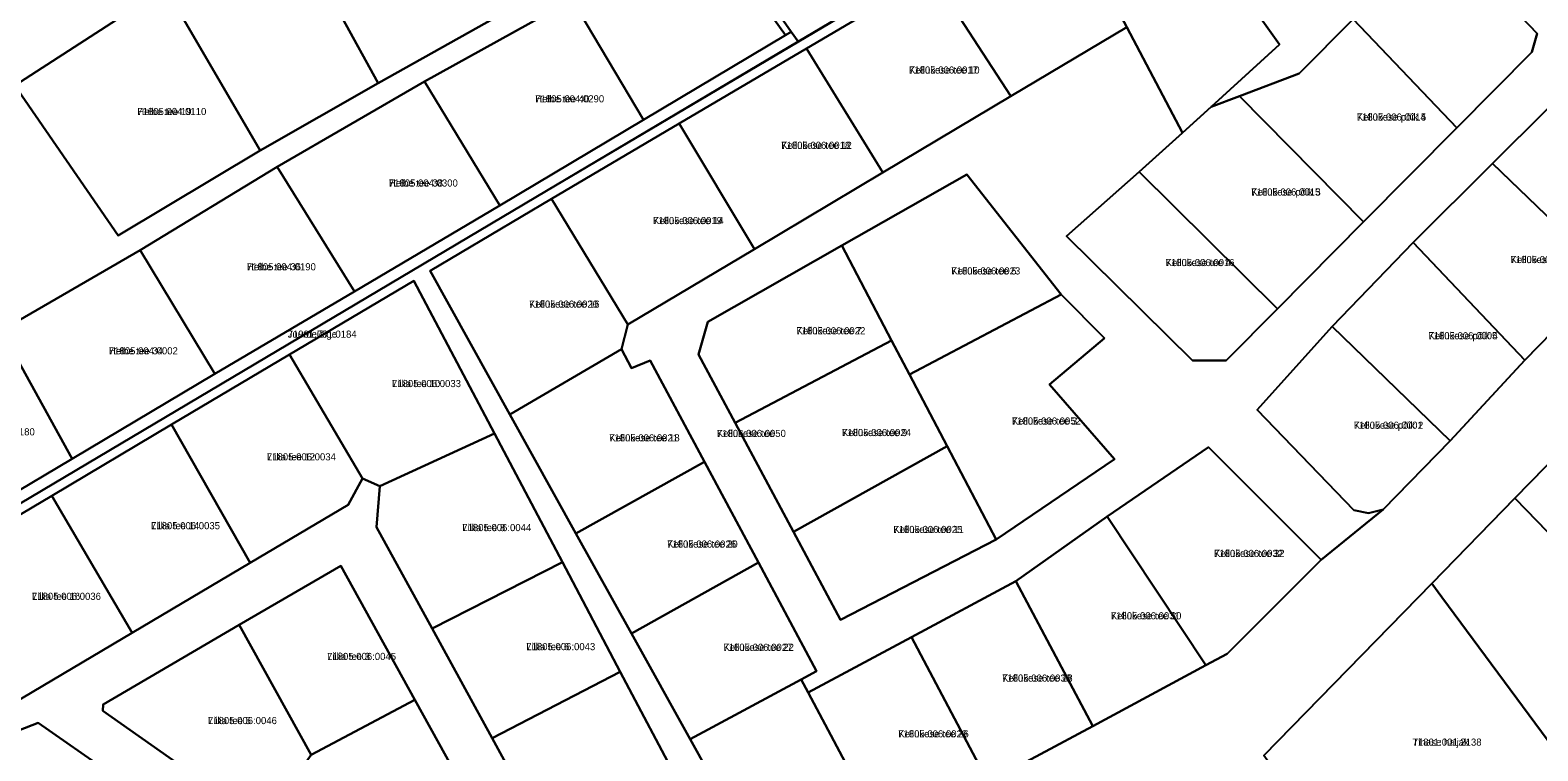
# Model space of a CAD drawing. Extents: x 529768 to 552006, y 6562269 to 6580975.
# Drawn here: x 537375.5 to 537692.6, y 6571224.9 to 6571376.5 of the extents above; entities that cross this region are included whole.
import ezdxf

# ---------------------------------------------------------------- set-up
doc = ezdxf.new("R2010")
doc.units = 0
for name, color, linetype in [('L_AADRESS', 7, 'Continuous'), ('PIIR', 7, 'Continuous'), ('TUNNUS', 7, 'Continuous')]:
    doc.layers.add(name, color=color, linetype=linetype)

msp = doc.modelspace()

# ---------------------------------------------------------------- linework, layer by layer
at = {"layer": 'PIIR'}
for points in [[(537702.86, 6571472.26), (537537.01, 6571374.1), (537535.57, 6571376.16), (537390.22, 6571584.9), (537364.81, 6571621.35)], [(537375.33, 6571521.4), (537398.03, 6571534.85), (537402.31, 6571540.45), (537378.19, 6571577.21), (537380.85, 6571578.91), (537390.22, 6571584.9), (537535.57, 6571376.16), (537534.34, 6571375.44), (537509.23, 6571410.51), (537508.1, 6571395.88), (537489.48, 6571382.98), (537458.45, 6571365.69), (537427.46, 6571347.74), (537398.65, 6571330.25), (537369.5, 6571313.34)], [(537362.92, 6571428.14), (537383.38, 6571396.32), (537393.59, 6571403.57), (537404.02, 6571385.41), (537372.3, 6571364.86), (537394.07, 6571333.31), (537423.89, 6571351.18), (537448.72, 6571365.38), (537475.12, 6571380.13), (537495.26, 6571392.55), (537500.44, 6571398.27), (537500.24, 6571405.38), (537484.63, 6571429.61), (537466.68, 6571455.44), (537448.53, 6571481.33), (537430.06, 6571506.65), (537412.22, 6571531.24), (537404.55, 6571531.74), (537378.26, 6571517.21), (537372.52, 6571514.07)], [(537512.12, 6571217.83), (537499.61, 6571241.55), (537487.46, 6571264.58), (537473.18, 6571291.64), (537456.21, 6571323.81), (537430.08, 6571308.29), (537405.24, 6571293.53), (537380.07, 6571278.58), (537354.9, 6571263.63), (537324.81, 6571245.7), (537323.81, 6571247.48), (537484.12, 6571342.72), (537702.86, 6571472.26)], [(537694.4, 6571359.72), (537683, 6571348.48), (537666.32, 6571331.83), (537649.3, 6571314.15), (537633.57, 6571296.66), (537653.88, 6571275.57), (537656.93, 6571274.93), (537660.06, 6571275.7), (537646.99, 6571265.1), (537623.28, 6571288.76), (537601.98, 6571274.19), (537582.81, 6571260.61), (537560.86, 6571248.83), (537539.13, 6571237.16), (537537.66, 6571239.95), (537540.92, 6571241.7), (537528.69, 6571264.52), (537517.34, 6571285.71), (537505.93, 6571307), (537502, 6571305.38), (537499.9, 6571309.41), (537501.25, 6571314.58), (537527.84, 6571330.44), (537554.85, 6571346.55), (537581.77, 6571362.6), (537606.13, 6571377.13), (537617.87, 6571354.91), (537608.71, 6571346.73), (537593.49, 6571333.16), (537619.94, 6571307.02), (537627.04, 6571307.05), (537637.81, 6571317.91), (537655.91, 6571336.16), (537675.56, 6571355.97), (537691.33, 6571371.87), (537692.43, 6571375.8), (537672.05, 6571397.14)], [(537565.14, 6571388.2), (537538.79, 6571372.65), (537512.01, 6571356.85), (537485.14, 6571341), (537459.65, 6571325.86), (537476.39, 6571295.7), (537490.32, 6571270.6), (537501.97, 6571249.62), (537514.31, 6571227.38), (537532.58, 6571194.47)], [(537577.01, 6571218.34), (537598.96, 6571230.13), (537622.75, 6571242.92), (537627.21, 6571245.31), (537646.99, 6571265.1), (537660.06, 6571275.7), (537674.15, 6571290.11), (537689.8, 6571307.09), (537707.34, 6571325.07)], [(537703.9, 6571294.61), (537687.75, 6571278.06), (537670.25, 6571260.12), (537634.95, 6571223.95)]]:
    msp.add_lwpolyline(points, dxfattribs=at)
for points in [[(537429.05, 6571428.91), (537442.51, 6571411.27), (537449.05, 6571414.78), (537450.48, 6571415.52), (537455.2, 6571408.66), (537475.12, 6571380.13), (537448.72, 6571365.38), (537418.16, 6571420.97)], [(537404.02, 6571385.41), (537393.59, 6571403.57), (537401.64, 6571409.33), (537418.16, 6571420.97), (537448.72, 6571365.38), (537423.89, 6571351.18)], [(537638.27, 6571373.5), (537623.86, 6571360.37), (537617.87, 6571354.91), (537606.13, 6571377.13), (537591.93, 6571404.01), (537609.33, 6571414.28), (537629.35, 6571386.06)], [(537672.05, 6571397.14), (537653.72, 6571378.82), (537642.37, 6571367.41), (537629.8, 6571362.63), (537623.86, 6571360.37), (537638.27, 6571373.5), (537629.35, 6571386.06), (537656.65, 6571413.26)], [(537489.48, 6571382.98), (537508.1, 6571395.88), (537509.23, 6571410.51), (537534.34, 6571375.44), (537504.53, 6571357.68)], [(537606.13, 6571377.13), (537581.77, 6571362.6), (537565.14, 6571388.2), (537591.93, 6571404.01)], [(537692.43, 6571375.8), (537691.33, 6571371.87), (537675.56, 6571355.97), (537653.72, 6571378.82), (537672.05, 6571397.14)], [(537554.85, 6571346.55), (537538.79, 6571372.65), (537565.14, 6571388.2), (537581.77, 6571362.6)], [(537423.89, 6571351.18), (537394.07, 6571333.31), (537372.3, 6571364.86), (537404.02, 6571385.41)], [(537458.45, 6571365.69), (537489.48, 6571382.98), (537504.53, 6571357.68), (537474.31, 6571339.66)], [(537535.57, 6571376.16), (537537.01, 6571374.1), (537484.12, 6571342.72), (537323.81, 6571247.48), (537322.52, 6571249.63), (537331.04, 6571254.5), (537333.2, 6571254.45), (537355.55, 6571269.2), (537384.35, 6571286.37), (537414.4, 6571304.23), (537443.78, 6571321.53), (537474.31, 6571339.66), (537504.53, 6571357.68), (537534.34, 6571375.44)], [(537655.91, 6571336.16), (537629.8, 6571362.63), (537642.37, 6571367.41), (537653.72, 6571378.82), (537675.56, 6571355.97)], [(537527.84, 6571330.44), (537512.01, 6571356.85), (537538.79, 6571372.65), (537554.85, 6571346.55)], [(537427.46, 6571347.74), (537458.45, 6571365.69), (537474.31, 6571339.66), (537443.78, 6571321.53)], [(537722.98, 6571341.36), (537707.34, 6571325.07), (537683, 6571348.48), (537694.4, 6571359.72), (537700.86, 6571366.1), (537707.79, 6571359.49)], [(537637.81, 6571317.91), (537608.71, 6571346.73), (537617.87, 6571354.91), (537623.86, 6571360.37), (537629.8, 6571362.63), (537655.91, 6571336.16)], [(537501.25, 6571314.58), (537485.14, 6571341), (537512.01, 6571356.85), (537527.84, 6571330.44)], [(537398.65, 6571330.25), (537427.46, 6571347.74), (537443.78, 6571321.53), (537414.4, 6571304.23)], [(537689.8, 6571307.09), (537666.32, 6571331.83), (537683, 6571348.48), (537707.34, 6571325.07)], [(537601.48, 6571311.69), (537592.34, 6571320.94), (537572.47, 6571346.14), (537546.23, 6571331.19), (537518.07, 6571315.15), (537516.09, 6571308.27), (537523.77, 6571293.89), (537536.06, 6571270.98), (537545.97, 6571252.46), (537578.65, 6571269.35), (537603.53, 6571286.29), (537589.86, 6571301.96)], [(537572.47, 6571346.14), (537592.34, 6571320.94), (537560.44, 6571304.09), (537556.68, 6571311.26), (537546.23, 6571331.19)], [(537627.04, 6571307.05), (537619.94, 6571307.02), (537593.49, 6571333.16), (537608.71, 6571346.73), (537637.81, 6571317.91)], [(537499.9, 6571309.41), (537476.39, 6571295.7), (537459.65, 6571325.86), (537485.14, 6571341), (537501.25, 6571314.58)], [(537649.3, 6571314.15), (537666.32, 6571331.83), (537689.8, 6571307.09), (537674.15, 6571290.11)], [(537369.5, 6571313.34), (537398.65, 6571330.25), (537414.4, 6571304.23), (537384.35, 6571286.37)], [(537516.09, 6571308.27), (537518.07, 6571315.15), (537546.23, 6571331.19), (537556.68, 6571311.26), (537523.77, 6571293.89)], [(537473.18, 6571291.64), (537449.08, 6571280.61), (537445.42, 6571282.22), (537430.08, 6571308.29), (537456.21, 6571323.81)], [(537601.48, 6571311.69), (537589.86, 6571301.96), (537603.53, 6571286.29), (537578.65, 6571269.35), (537568.34, 6571289.02), (537560.44, 6571304.09), (537592.34, 6571320.94)], [(537342.32, 6571290.8), (537343.3, 6571297.87), (537369.5, 6571313.34), (537384.35, 6571286.37), (537355.55, 6571269.2)], [(537633.57, 6571296.66), (537649.3, 6571314.15), (537674.15, 6571290.11), (537660.06, 6571275.7), (537656.93, 6571274.93), (537653.88, 6571275.57)], [(537568.34, 6571289.02), (537536.06, 6571270.98), (537523.77, 6571293.89), (537556.68, 6571311.26), (537560.44, 6571304.09)], [(537445.42, 6571282.22), (537442.4, 6571276.69), (537421.84, 6571264.48), (537405.24, 6571293.53), (537430.08, 6571308.29)], [(537502, 6571305.38), (537505.93, 6571307), (537517.34, 6571285.71), (537490.32, 6571270.6), (537476.39, 6571295.7), (537499.9, 6571309.41)], [(537687.75, 6571278.06), (537703.9, 6571294.61), (537706.25, 6571292.01), (537736.91, 6571258.07), (537720.08, 6571244.65), (537690.18, 6571275.55)], [(537421.84, 6571264.48), (537396.97, 6571249.71), (537380.07, 6571278.58), (537405.24, 6571293.53)], [(537487.46, 6571264.58), (537460.05, 6571250.62), (537448.36, 6571271.95), (537449.08, 6571280.61), (537473.18, 6571291.64)], [(537578.65, 6571269.35), (537545.97, 6571252.46), (537536.06, 6571270.98), (537568.34, 6571289.02)], [(537601.98, 6571274.19), (537623.28, 6571288.76), (537646.99, 6571265.1), (537627.21, 6571245.31), (537622.75, 6571242.92)], [(537528.69, 6571264.52), (537501.97, 6571249.62), (537490.32, 6571270.6), (537517.34, 6571285.71)], [(537500.31, 6571177.14), (537489.99, 6571171.59), (537474.12, 6571163.07), (537443.9, 6571184.21), (537419.45, 6571201.31), (537395.3, 6571218.2), (537377.23, 6571230.84), (537343.75, 6571217.76), (537339.6, 6571220.7), (537371.86, 6571234.8), (537396.97, 6571249.71), (537421.84, 6571264.48), (537442.4, 6571276.69), (537445.42, 6571282.22), (537449.08, 6571280.61), (537448.36, 6571271.95), (537460.05, 6571250.62), (537472.66, 6571227.61), (537485.53, 6571204.11)], [(537396.97, 6571249.71), (537371.86, 6571234.8), (537354.9, 6571263.63), (537380.07, 6571278.58)], [(537670.25, 6571260.12), (537687.75, 6571278.06), (537690.18, 6571275.55), (537720.08, 6571244.65), (537695.95, 6571225.42), (537672.36, 6571257.27)], [(537582.81, 6571260.61), (537601.98, 6571274.19), (537622.75, 6571242.92), (537598.96, 6571230.13)], [(537390.85, 6571233.33), (537424.42, 6571209.69), (537460.83, 6571184.07), (537479.5, 6571193.94), (537456.44, 6571235.68), (537440.86, 6571263.86), (537419.53, 6571251.4), (537390.92, 6571234.67)], [(537440.86, 6571263.86), (537456.44, 6571235.68), (537434.62, 6571224.09), (537419.53, 6571251.4)], [(537499.61, 6571241.55), (537472.66, 6571227.61), (537460.05, 6571250.62), (537487.46, 6571264.58)], [(537540.92, 6571241.7), (537537.66, 6571239.95), (537514.31, 6571227.38), (537501.97, 6571249.62), (537528.69, 6571264.52)], [(537560.86, 6571248.83), (537582.81, 6571260.61), (537598.96, 6571230.13), (537577.01, 6571218.34)], [(537670.25, 6571260.12), (537672.36, 6571257.27), (537695.95, 6571225.42), (537696.81, 6571219.49), (537660.25, 6571193.6), (537657.8, 6571191.87), (537634.95, 6571223.95)], [(537390.85, 6571233.33), (537390.92, 6571234.67), (537419.53, 6571251.4), (537434.62, 6571224.09), (537424.42, 6571209.69)], [(537539.13, 6571237.16), (537560.86, 6571248.83), (537577.01, 6571218.34), (537555.3, 6571206.68)], [(537512.12, 6571217.83), (537485.53, 6571204.11), (537472.66, 6571227.61), (537499.61, 6571241.55)], [(537537.66, 6571239.95), (537539.13, 6571237.16), (537555.3, 6571206.68), (537532.58, 6571194.47), (537514.31, 6571227.38)], [(537479.5, 6571193.94), (537460.83, 6571184.07), (537424.42, 6571209.69), (537434.62, 6571224.09), (537456.44, 6571235.68)], [(537377.23, 6571230.84), (537395.3, 6571218.2), (537377.95, 6571193.89), (537365.05, 6571202.83), (537343.75, 6571217.76)]]:
    msp.add_lwpolyline(points, close=True, dxfattribs=at)

# ---------------------------------------------------------------- texts
at = {"layer": 'L_AADRESS'}
for s, p in [('Kellukese tee 10', (537560.35, 6571367.38)), ('Helbe tee 40', (537481.74, 6571361.32)), ('Helbe tee 19', (537398.09, 6571358.65)), ('Kellukese põik 5', (537654.49, 6571357.49)), ('Kellukese tee 12', (537533.48, 6571351.54)), ('Helbe tee 38', (537450.97, 6571343.61)), ('Kellukese põik 3', (537632.31, 6571341.72)), ('Kellukese tee 14', (537506.52, 6571335.71)), ('Kellukese põik 6', (537686.83, 6571327.51)), ('Helbe tee 36', (537421.12, 6571325.99)), ('Kellukese tee 5', (537569.23, 6571325.12)), ('Kellukese tee 4', (537614.3, 6571326.88)), ('Kellukese tee 16', (537480.45, 6571318.14)), ('Juurdelõige', (537429.7, 6571311.82)), ('Kellukese tee 7', (537536.66, 6571312.54)), ('Kellukese põik 4', (537669.55, 6571311.49)), ('Helbe tee 34', (537392.1, 6571308.31)), ('Liilia tee 10', (537451.63, 6571301.43)), ('Kellukese tee 3', (537581.98, 6571293.55)), ('Kellukese põik 2', (537653.86, 6571292.66)), ('Kellukese tee 18', (537497.29, 6571290.01)), ('Kellukese tee', (537519.95, 6571290.94)), ('Kellukese tee 9', (537546.25, 6571291.12)), ('Liilia tee 12', (537425.33, 6571286.01)), ('Liilia tee 14', (537400.96, 6571271.53)), ('Liilia tee 8', (537466.41, 6571271.13)), ('Kellukese tee 11', (537557.05, 6571270.74)), ('Kellukese tee 20', (537509.48, 6571267.67)), ('Kellukese tee 32', (537624.48, 6571265.7)), ('Liilia tee 16', (537375.93, 6571256.67)), ('Kellukese tee 30', (537602.78, 6571252.58)), ('Liilia tee 6', (537479.87, 6571246.09)), ('Kellukese tee 22', (537521.32, 6571245.95)), ('Liilia tee 3', (537437.98, 6571244.03)), ('Kellukese tee 28', (537579.91, 6571239.48)), ('Liilia tee 5', (537412.93, 6571230.54)), ('Kellukese tee 26', (537558.07, 6571227.75)), ('Tihase haljak', (537666.23, 6571226))]:
    msp.add_text(s, height=1.5, dxfattribs=at).set_placement(p)
at = {"layer": 'TUNNUS'}
for s, p in [('71805:006:0017', (537560.35, 6571367.38)), ('71805:004:0290', (537481.74, 6571361.32)), ('71805:004:0110', (537398.09, 6571358.65)), ('71805:006:0014', (537654.49, 6571357.49)), ('71805:006:0018', (537533.48, 6571351.54)), ('71805:004:0300', (537450.97, 6571343.61)), ('71805:006:0015', (537632.31, 6571341.72)), ('71805:006:0019', (537506.52, 6571335.71)), ('71805:006:0049', (537686.83, 6571327.51)), ('71805:004:0190', (537421.12, 6571325.99)), ('71805:006:0023', (537569.23, 6571325.12)), ('71805:006:0016', (537614.3, 6571326.88)), ('71805:006:0020', (537480.45, 6571318.14)), ('71901:001:0184', (537429.7, 6571311.82)), ('71805:006:0022', (537536.66, 6571312.54)), ('71805:006:0005', (537669.55, 6571311.49)), ('71805:004:0002', (537392.1, 6571308.31)), ('71805:006:0033', (537451.63, 6571301.43)), ('71805:006:0052', (537581.98, 6571293.55)), ('71805:006:0001', (537653.86, 6571292.66)), ('71805:004:0180', (537362.02, 6571291.27)), ('71805:006:0021', (537497.29, 6571290.01)), ('71805:006:0050', (537519.95, 6571290.94)), ('71805:006:0024', (537546.25, 6571291.12)), ('71805:006:0034', (537425.33, 6571286.01)), ('71805:006:0035', (537400.96, 6571271.53)), ('71805:006:0044', (537466.41, 6571271.13)), ('71805:006:0025', (537557.05, 6571270.74)), ('71805:006:0026', (537509.48, 6571267.67)), ('71805:006:0032', (537624.48, 6571265.7)), ('71805:006:0036', (537375.93, 6571256.67)), ('71805:006:0031', (537602.78, 6571252.58)), ('71805:006:0043', (537479.87, 6571246.09)), ('71805:006:0027', (537521.32, 6571245.95)), ('71805:006:0045', (537437.98, 6571244.03)), ('71805:006:0030', (537579.91, 6571239.48)), ('71805:006:0046', (537412.93, 6571230.54)), ('71805:006:0029', (537558.07, 6571227.75)), ('71801:001:2138', (537666.23, 6571226))]:
    msp.add_text(s, height=1.5, dxfattribs=at).set_placement(p)

doc.saveas('drawing.dxf')
